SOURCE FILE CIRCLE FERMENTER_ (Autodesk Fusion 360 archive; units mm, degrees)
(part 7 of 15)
sketch "Schizzo22" plane through (0, -90, 0) normal (0, -1, 0) x axis (1, 0, 0)
  line L1 (160, -63.5) -> (85, -63.5)
  line L2 (160, 91.5) -> (160, -63.5)
  line L3 (85, 91.5) -> (160, 91.5)
  line L4 (0, 91.5) -> (85, 91.5)
  line L5 (0, 81.5) -> (0, 91.5)
  line L6 (95, 81.5) -> (0, 81.5)
  curve K1 (125, 51.5) -> (95, 81.5)
  line L7 (125, -23.5) -> (125, 51.5)
  curve K2 (125, -23.5) -> (95, -53.5)
  line L8 (0, -53.5) -> (95, -53.5)
  line L9 (0, -63.5) -> (0, -53.5)
  line L10 (85, -63.5) -> (0, -63.5)
  line L11 (142, 80) -> (0, 80)
  line L12 (0, 64) -> (142, 64)
  line L13 (0, 80) -> (0, 64)
  curve K3 (140.5791, 76.7542) -> (140.5791, 75.2458)
  curve K4 (143, 79) -> (142, 80)
  line L14 (143, 65) -> (143, 79)
  curve K5 (142, 64) -> (143, 65)
  circle C1 centre (47.5, 86.5) radius 3.35
  circle C2 centre (130, 51.5) radius 3.35
  circle C3 centre (130, -23.5) radius 3.35
  circle C4 centre (47.5, -58.5) radius 3.35
  circle C5 centre (139, 76) radius 1.5
  circle C6 centre (139, 68) radius 1.5
  arc A1 centre (139, 76) radius 1.75 clockwise from (140.5791, 76.7542) to (140.5791, 75.2458)
  circle C7 centre (139, 76) radius 1.75
  circle C8 centre (139, 68) radius 1.75
  circle C9 centre (139, 76) radius 1.75
  circle C10 centre (139, 68) radius 1.75
  concentric C5 A1
  concentric C6 C8
  dimension "d743_1" diameter C5 = 3
  dimension "d744_1" diameter C6 = 3
offset_faces "FacceDiOffset2" distance 1 named "d748_1"
extrude "Estrusione18" cut sketch "Schizzo22" profile of C5 C6 blind -7.192 named "d746_1" from offset -0.8 named "d745_1"
component_from_bodies "Corpo->Comp1"
component_from_bodies "Corpo->Comp2"
copy_paste "CopiaIncolla1"
copy_paste "CopiaIncolla2"
sketch "Schizzo23" plane through (0, -90, 0) normal (0, -1, 0) x axis (1, 0, 0)
  line L1 (160, -63.5) -> (85, -63.5)
  line L2 (160, 91.5) -> (160, -63.5)
  line L3 (85, 91.5) -> (160, 91.5)
  line L4 (0, 91.5) -> (85, 91.5)
  line L5 (0, 81.5) -> (0, 91.5)
  line L6 (95, 81.5) -> (0, 81.5)
  curve K1 (125, 51.5) -> (95, 81.5)
  line L7 (125, -23.5) -> (125, 51.5)
  curve K2 (125, -23.5) -> (95, -53.5)
  line L8 (0, -53.5) -> (95, -53.5)
  line L9 (0, -63.5) -> (0, -53.5)
  line L10 (85, -63.5) -> (0, -63.5)
  circle C1 centre (47.5, 86.5) radius 3.35
  circle C2 centre (130, 51.5) radius 3.35
  circle C3 centre (130, -23.5) radius 3.35
  circle C4 centre (47.5, -58.5) radius 3.35
  circle C5 centre (139, -4) radius 1.5
  circle C6 centre (139, -12) radius 1.5
  circle C7 centre (139, -12) radius 1.75
  circle C8 centre (139, -4) radius 1.75
  circle C9 centre (139, -12) radius 1.75
  point P19 (139, -12)
  point P20 (139, -12)
  concentric C5 C8
  coincident P19 P20
  dimension "d749_1" diameter C5 = 3
  dimension "d750_1" diameter C6 = 3
extrude "Estrusione19" cut sketch "Schizzo23" profile of C5 C6 against normal blind 9.545 named "d751_1"
sketch "Schizzo24" plane through (0, -88.4, 0) normal (0, 1, 0) x axis (-1, 0, 0)
  line L1 (-140.6, 91.5) -> (-140.6, -63.5)
  line L2 (-150.8209, 91.5) -> (-140.6, 91.5)
  line L3 (-150.8209, 41.5) -> (-150.8209, 91.5)
  line L4 (-150.8209, -13.5) -> (-150.8209, 41.5)
  line L5 (-150.8209, -13.5) -> (-150.8209, -63.5)
  line L6 (-140.6, -63.5) -> (-150.8209, -63.5)
  line L7 (-160, -63.5) -> (-85, -63.5)
  line L8 (-160, 91.5) -> (-160, -63.5)
  line L9 (-85, 91.5) -> (-160, 91.5)
  line L10 (0, 91.5) -> (-85, 91.5)
  line L11 (0, 81.5) -> (0, 91.5)
  line L12 (-95, 81.5) -> (0, 81.5)
  curve K1 (-125, 51.5) -> (-95, 81.5)
  line L13 (-125, -23.5) -> (-125, 51.5)
  curve K2 (-125, -23.5) -> (-95, -53.5)
  line L14 (0, -53.5) -> (-95, -53.5)
  line L15 (0, -63.5) -> (0, -53.5)
  line L16 (-85, -63.5) -> (0, -63.5)
  line L17 (-139, 78.5) -> (-139, -14.5)
  circle C1 centre (-139, 76) radius 1.5
  circle C2 centre (-139, 68) radius 1.5
  circle C3 centre (-139, 68) radius 2.5
  circle C4 centre (-139, 76) radius 2.5
  circle C5 centre (-139, -4) radius 1.5
  circle C6 centre (-139, -12) radius 1.5
  circle C7 centre (-139, -4) radius 1.5
  circle C8 centre (-139, -12) radius 1.5
  circle C9 centre (-47.5, 86.5) radius 3.35
  circle C10 centre (-130, 51.5) radius 3.35
  circle C11 centre (-130, -23.5) radius 3.35
  circle C12 centre (-47.5, -58.5) radius 3.35
  circle C13 centre (-139, -4) radius 2.5
  circle C14 centre (-139, -12) radius 2.5
  point P34 (-139, -14.5)
  point P35 (-139, 78.5)
  concentric C2 C3
  concentric C1 C4
  concentric C5 C13
  concentric C8 C14
  coincident C14 P34
  coincident C4 P35
  vertical L17
  dimension "d758_1" diameter C3 = 5
  dimension "d759_1" diameter C4 = 5
  dimension "d760_1" diameter C13 = 5
  dimension "d761_1" diameter C14 = 5
extrude "Estrusione20" add sketch "Schizzo24" profile of L1 C1 C2 C3 C4 C5 C6 C7 C8 C13 C14 L17 to an object
sketch "Schizzo25" plane through (0, -90, 0) normal (0, -1, 0) x axis (1, 0, 0)
  line L1 (160, -63.5) -> (85, -63.5)
  line L2 (160, 91.5) -> (160, -63.5)
  line L3 (85, 91.5) -> (160, 91.5)
  line L4 (0, 91.5) -> (85, 91.5)
  line L5 (0, 81.5) -> (0, 91.5)
  line L6 (95, 81.5) -> (0, 81.5)
  curve K1 (125, 51.5) -> (95, 81.5)
  line L7 (125, -23.5) -> (125, 51.5)
  curve K2 (125, -23.5) -> (95, -53.5)
  line L8 (0, -53.5) -> (95, -53.5)
  line L9 (0, -63.5) -> (0, -53.5)
  line L10 (85, -63.5) -> (0, -63.5)
  curve K3 (139, -2.5) -> (139, -2.5)
  circle C1 centre (139, -4) radius 1.5
  circle C2 centre (139, -12) radius 1.5
  circle C3 centre (47.5, 86.5) radius 3.35
  circle C4 centre (130, 51.5) radius 3.35
  circle C5 centre (130, -23.5) radius 3.35
  circle C6 centre (47.5, -58.5) radius 3.35
  circle C7 centre (139, -12) radius 1.5
extrude "Estrusione21" add sketch "Schizzo25" profile of C1 C2 K3 C7 against normal blind 0.8 named "d765_1"
work_plane "Piano di lavoro7" AlongDistance -5 named "d767_1"
sketch "Schizzo26" plane through (0, -85, 0) normal (0, -1, 0) x axis (-1, 0, 0)
  curve K1 (-140.3526, 4.6485) -> (-140.4601, 4.3436)
  circle C1 centre (-139, -76) radius 1.5
  circle C2 centre (-139, -68) radius 1.5
  circle C3 centre (-139, 12) radius 1.5
  circle C4 centre (-139, 4) radius 2.3
  circle C5 centre (-139, 12) radius 2.3
  circle C6 centre (-139, -68) radius 2.3
  circle C7 centre (-139, -76) radius 2.3
  arc A1 centre (-139, 4) radius 1.5 clockwise from (-140.3526, 4.6485) to (-140.4601, 4.3436)
  concentric C3 C5
  concentric C2 C6
  concentric C1 C7
  dimension "d768_1" diameter C4 = 4.6
  dimension "d769_1" diameter C5 = 4.6
  dimension "d770_1" diameter C6 = 4.6
  dimension "d771_1" diameter C7 = 4.6
extrude "Estrusione22" cut sketch "Schizzo26" profile of C1 C2 C3 C4 C5 C6 C7 against normal blind 5.06 named "d772_1"
sketch "Schizzo27" plane through (0, -85, 0) normal (0, 1, 0) x axis (-1, 0, 0)
  line L1 (-137.1434, -13.3576) -> (-137.1434, -10.6424)
  line L2 (-137.1434, -5.3576) -> (-137.1434, -2.6424)
  line L3 (-137.1434, 74.6424) -> (-137.1434, 77.3576)
  line L4 (-137.1434, 66.6424) -> (-137.1434, 69.3576)
  arc A1 centre (-139, -12) radius 2.3 clockwise from (-137.1434, -13.3576) to (-137.1434, -10.6424)
  circle C1 centre (-139, -12) radius 1.5
  arc A2 centre (-139, -4) radius 2.3 clockwise from (-137.1434, -5.3576) to (-137.1434, -2.6424)
  circle C2 centre (-139, -4) radius 1.5
  arc A3 centre (-139, 76) radius 2.3 clockwise from (-137.1434, 74.6424) to (-137.1434, 77.3576)
  circle C3 centre (-139, 76) radius 1.5
  arc A4 centre (-139, 68) radius 2.3 clockwise from (-137.1434, 66.6424) to (-137.1434, 69.3576)
  circle C4 centre (-139, 68) radius 1.5
  circle C5 centre (-139, 68) radius 2
  circle C6 centre (-139, 76) radius 2
  circle C7 centre (-139, -4) radius 2
  circle C8 centre (-139, -12) radius 2
  concentric A4 C5
  concentric A3 C6
  concentric A2 C7
  concentric A1 C8
  dimension "d792_1" diameter C5 = 4
  dimension "d793_1" diameter C6 = 4
  dimension "d794_1" diameter C7 = 4
  dimension "d795_1" diameter C8 = 4
extrude "Estrusione24" cut sketch "Schizzo27" profile of L1 C1 L2 C2 L3 C3 L4 C4 C5 C6 C7 C8 against normal blind 4.2 named "d796_1"
extrude "Estrusione25" add sketch "Schizzo2" to an object
extrude "Estrusione26" add sketch "Schizzo3" against normal blind 155 named "d848_1"
extrude "Estrusione27" add sketch "Schizzo4" profile of L1 L3 A1 L11 L12 L13 A2 L14 A3 L15 A4 L16 A5 L17 A6 L18 A7 L19 A8 L20 L21 L22 against normal blind 7 named "d850_1"
mirror "Specchio2" mirrorStitchTolerance 0.1 named "d710_1"
mirror "Specchio2" mirrorStitchTolerance 0.1 named "d777_1"
component_from_bodies "Corpo->Comp1"
base_feature "Lavorazione di base1"
sketch "Schizzo2" plane through (0, 88.4, 0) normal (0, -1, 0) x axis (1, 0, 0)
  line L1 (0, -53.5) -> (95, -53.5)
  line L2 (0, -63.5) -> (0, -53.5)
  line L3 (95, -63.5) -> (0, -63.5)
  curve K1 (95, -63.5) -> (135, -23.5)
  line L4 (135, 51.5) -> (135, -23.5)
  curve K2 (95, 91.5) -> (135, 51.5)
  line L5 (0, 91.5) -> (95, 91.5)
  line L6 (0, 81.5) -> (0, 91.5)
  line L7 (95, 81.5) -> (0, 81.5)
  curve K3 (125, 51.5) -> (95, 81.5)
  line L8 (125, -23.5) -> (125, 51.5)
  curve K4 (125, -23.5) -> (95, -53.5)
  line L9 (95, -63) -> (0, -63)
  curve K5 (95, -63) -> (134.5, -23.5)
  line L10 (134.5, 51.5) -> (134.5, -23.5)
  line L11 (0, 91) -> (0, -63)
  curve K6 (95, 91) -> (134.5, 51.5)
  line L12 (0, 91) -> (95, 91)
  circle C1 centre (47.5, 86.5) radius 1.75
  circle C2 centre (130, 51.5) radius 1.75
  circle C3 centre (130, -23.5) radius 1.75
  circle C4 centre (47.5, -58.5) radius 1.75
  point P24 (0, 91)
  coincident L6 P24
  perpendicular L9 L11
  dimension "d782_1" = -0.5
  dimension "d785_1" = -0.5
extrude "Estrusione2" new body sketch "Schizzo2" profile of C1 C2 C3 C4 L1 L2 L6 L7 K3 L8 K4 K5 L9 L10 L11 L12 K6 along normal blind 3 named "d783_1"
component_from_bodies "Corpo->Comp2"
copy_paste "CopiaIncolla2"
joint "Assembla2" alignAngle 0 named "d786_1" alignOffsetX 0 named "d787_1" alignOffsetY 0 named "d788_1" alignOffsetZ 0 named "d789_1"
remove_instance "RimuoviIstanza1"
component_from_bodies "Corpo->Comp1"
base_feature "Lavorazione di base1" bodies "PROFILO BASE"
mirror "Specchio1" mirrorStitchTolerance 0.1 named "d819_1"
mirror "Specchio1" mirrorStitchTolerance 0.1 named "d821_2"
mirror_component "SpecchiaComponente1"
derived_instance "DerivedInstance1"
mirror_component "SpecchiaComponente2"
derived_instance "DerivedInstance2"
mirror "Specchio1" mirrorStitchTolerance 0.1 named "d823_1"
mirror_component "SpecchiaComponente3"
derived_instance "DerivedInstance3"
derived_instance "DerivedInstance4"
derived_instance "DerivedInstance5"
derived_instance "DerivedInstance6"
sketch "Schizzo1" plane through (0, -72.4, 0) normal (0, 1, 0) x axis (-1, 0, 0)
  line L1 (142, 64) -> (-142, 64)
  curve K1 (142, 64) -> (143, 65)
  line L2 (143, 79) -> (143, 65)
  curve K2 (143, 79) -> (142, 80)
  line L3 (-142, 80) -> (142, 80)
  curve K3 (-143, 79) -> (-142, 80)
  line L4 (-143, 65) -> (-143, 79)
  curve K4 (-142, 64) -> (-143, 65)
  line L5 (142, 64) -> (-142, 64)
  curve K5 (142, 64) -> (143, 65)
  line L6 (143, 79) -> (143, 65)
  curve K6 (143, 79) -> (142, 80)
  line L7 (-142, 80) -> (142, 80)
  curve K7 (-143, 79) -> (-142, 80)
  line L8 (-143, 65) -> (-143, 79)
  curve K8 (-142, 64) -> (-143, 65)
  circle C1 centre (139, 76) radius 1.75
  circle C2 centre (139, 68) radius 1.75
  circle C3 centre (-139, 68) radius 1.75
  circle C4 centre (-139, 76) radius 1.75
  circle C5 centre (139, 76) radius 1.75
  circle C6 centre (139, 68) radius 1.75
  circle C7 centre (-139, 68) radius 1.75
  circle C8 centre (-139, 76) radius 1.75
joint "Assembla4" alignAngle 0 named "d903_1" alignOffsetX 0 named "d904_1" alignOffsetY 0 named "d905_1" alignOffsetZ 0 named "d906_1"
sketch "Schizzo1" plane through (0, 0, -88.5) normal (0, 0, -1) x axis (1, 0, 0)
  line L1 (95, 55) -> (0, 55)
  curve K1 (95, 55) -> (125, 25)
  line L2 (125, -25) -> (125, 25)
  curve K2 (95, -55) -> (125, -25)
  line L3 (0, -55) -> (95, -55)
  line L4 (0, -65) -> (0, -55)
  line L5 (85, -65) -> (0, -65)
  line L6 (160, -65) -> (85, -65)
  line L7 (160, 65) -> (160, -65)
  line L8 (85, 65) -> (160, 65)
  line L9 (0, 65) -> (85, 65)
  line L10 (0, 55) -> (0, 65)
  curve K3 (95, -55) -> (125, -25)
  line L11 (95, -55) -> (0, -55)
  line L12 (125, -25) -> (125, 25)
  line L13 (135, -25) -> (135, 0)
  curve K4 (95, -65) -> (135, -25)
  line L14 (95, -65) -> (0, -65)
  line L15 (135, 0) -> (125, 0)
  line L16 (122, -25) -> (122, 0)
  curve K5 (95, -52) -> (122, -25)
  line L17 (95, -52) -> (0, -52)
  line L18 (122, 0) -> (125, 0)
  line L19 (0, -52) -> (0, -65)
  circle C1 centre (47.5, -60) radius 3.35
  circle C2 centre (130, -25) radius 3.35
  circle C3 centre (130, 25) radius 3.35
  circle C4 centre (47.5, 60) radius 3.35
  circle C5 centre (130, -25) radius 1.75
  circle C6 centre (47.5, -60) radius 1.75
  point P25 (125, 0)
  point P12 (0, -65)
  point P31 (0, -65)
  midpoint L2 P25
  perpendicular L13 L15
  perpendicular L16 L18
  coincident P12 P31
  perpendicular L17 L19
extrude "Estrusione1" new body sketch "Schizzo1" profile of C1 C2 L2 K2 L3 L4 L5 L6 K3 L11 L12 L13 K4 L14 L15 L16 K5 L17 L18 L19 C5 C6 along normal blind 15 named "d826_1"
sketch "Schizzo2" plane through (0, 0, 0) normal (0, -1, 0) x axis (1, 0, 0)
  line L1 (122, -88.5) -> (135, -88.5)
  line L2 (122, -103.5) -> (122, -88.5)
  line L3 (135, -103.5) -> (122, -103.5)
  line L4 (135, -88.5) -> (135, -103.5)
  line L5 (124, -88.5) -> (124, -103.5)
  curve K1 (135, -91) -> (135, -88.5)
  curve K2 (129.5, -94.5) -> (135, -91)
  curve K3 (124, -99.2) -> (129.5, -94.5)
  curve K4 (124, -101.7) -> (124, -99.2)
  curve K5 (124, -101.7) -> (135, -88.5)
  line L6 (124, -103.5) -> (124, -101.7)
  point P6 (124, -103.5)
  point P7 (124, -88.5)
  point P8 (135, -91)
  point P10 (124, -99.2)
  point P2 (135, -88.5)
  point P9 (129.5, -94.5)
  point P11 (124, -101.7)
  coincident L3 P6
  coincident L1 P7
  perpendicular L1 L5
  coincident L4 P8
  coincident L5 P10
  vertical K4
  dimension "d828_1" distance L2 L5 = 2
  dimension "d830_1" distance P2 P8 = 2.5
  dimension "d831_1" distance P8 P9 = 3.5
  dimension "d832_1" distance P9 P10 = 4.7
  dimension "d833_1" distance L4 P9 = 5.5 (= "d881_1 / 2")
  dimension "d852_1" distance P6 P11 = 1.8
  dimension "d853_1" distance P10 P11 = 2.5
  dimension "d881_1" distance L4 L5 = 11
sweep "Sweep1" sketch "Schizzo2" TwistAngle 0 named "d838_1" TaperAngle 0 named "d839_1"
sketch "Schizzo3" plane through (0, 0, -88.5) normal (0, 0, 1) x axis (-1, 0, 0)
  line L1 (0, -65) -> (-95, -65)
  line L2 (0, -52) -> (0, -65)
  line L3 (-95, -52) -> (0, -52)
  curve K1 (-95, -52) -> (-122, -25)
  line L4 (-122, 0) -> (-122, -25)
  line L5 (-135, 0) -> (-122, 0)
  line L6 (-135, -25) -> (-135, 0)
  curve K2 (-95, -65) -> (-135, -25)
  line L7 (-95, -54.4) -> (0, -54.4)
  curve K3 (-95, -54.4) -> (-124.4, -25)
  line L8 (-124.4, 0) -> (-124.4, -25)
  line L9 (-122, 0) -> (-124.4, 0)
  line L10 (0, -54.4) -> (0, -52)
  circle C1 centre (-130, -25) radius 1.75
  circle C2 centre (-47.5, -60) radius 1.75
  point P9 (-122, 0)
  point P16 (-122, 0)
  point P6 (0, -52)
  point P17 (0, -52)
  coincident P9 P16
  perpendicular L4 L9
  coincident P6 P17
  perpendicular L7 L10
  dimension "d840_1" = -2.4
extrude "Estrusione2" add sketch "Schizzo3" profile of L2 L3 K1 L4 L5 L8 L7 K3 L9 L10 along normal blind 1.6 named "d841_1"
extrude "Estrusione4" cut of existing geometry blind -0.2 named "d854_1"
work_plane "Piano di lavoro1" AlongDistance -1.2 named "d856_1"
sketch "Schizzo5" plane through (0, 0, -89.7) normal (0, 0, 1) x axis (1, 0, 0)
  circle C1 centre (130, 25) radius 3
  circle C2 centre (47.5, 60) radius 3
  circle C3 centre (47.5, 60) radius 1.75
  circle C4 centre (130, 25) radius 1.75
  point P3 (47.5, 60)
  point P4 (47.5, 60)
  point P2 (130, 25)
  point P5 (130, 25)
  coincident P3 P4
  coincident P2 P5
  dimension "d857_1" diameter C1 = 6
  dimension "d858_1" diameter C2 = 6 (= "d857_1")
extrude "Estrusione5" cut sketch "Schizzo5" profile of C1 C2 C3 against normal blind 16.363 named "d860_1"
joint "Assembla5" alignAngle 0 named "d1241_1" alignOffsetX 0 named "d1242_1" alignOffsetY 0 named "d1243_1" alignOffsetZ 0 named "d1244_1"
chamfer "Smusso1" distance 1.25 named "d862_1"
fillet "Raccordo1" radius 0.2 named "d864_1"
extrude "Estrusione6" cut of existing geometry blind -1.4 named "d865_1"
sketch "Schizzo6" plane through (0, 0, 0) normal (0, -1, 0) x axis (1, 0, 0)
  line L1 (122, -88.5) -> (135, -88.5)
  line L2 (122, -103.5) -> (122, -88.5)
  line L3 (124, -103.5) -> (122, -103.5)
  line L4 (124, -101.7) -> (124, -103.5)
  curve K1 (135, -88.5) -> (124, -101.7)
  line L5 (122, -101.7) -> (124, -101.7)
  line L6 (124.4, -88.5) -> (122, -88.5)
  curve K2 (124.4, -91.5) -> (124.4, -88.5)
  curve K3 (123.2, -95.1) -> (124.4, -91.5)
  curve K4 (122, -98.7) -> (123.2, -95.1)
  curve K5 (122, -101.7) -> (122, -98.7)
  curve K6 (122, -101.7) -> (124.4, -88.5)
  point P6 (124, -101.7)
  point P7 (124, -101.7)
  point P8 (122, -101.7)
  point P3 (122, -88.5)
  point P9 (122, -88.5)
  point P10 (124.4, -88.5)
  point P13 (122, -98.7)
  point P11 (124.4, -91.5)
  point P12 (123.2, -95.1)
  coincident P6 P7
  coincident L2 P8
  perpendicular L2 L5
  coincident P3 P9
  coincident L1 P10
  vertical K5
  vertical K2
  dimension "d867_1" distance P9 P10 = 2.4
  dimension "d868_1" distance P8 P13 = 3
  dimension "d869_1" distance P10 P11 = 3
  dimension "d870_1" distance P11 P12 = 3.6 (= "d873_1 / 2")
  dimension "d873_1" distance P11 P13 = 7.2
  dimension "d874_1" distance L2 P12 = 1.2 (= "d867_1 / 2")
sweep "Sweep2" sketch "Schizzo6" TwistAngle 0 named "d879_1" TaperAngle 0 named "d880_1"
mirror "Specchio1" mirrorStitchTolerance 0.1 named "d883_1"
mirror "Specchio2" mirrorStitchTolerance 0.1 named "d885_1"
component_from_bodies "Corpo->Comp1"
component_from_bodies "Corpo->Comp2"
sketch "Schizzo1" plane through (0, 0, 0) normal (-1, 0, 0) x axis (0, -1, 0)
  curve K1 (-52, -101.7) -> (-54.4, -88.5)
  line L1 (-65, -88.5) -> (-54.4, -88.5)
  curve K2 (-54, -101.7) -> (-65, -88.5)
  line L2 (-54, -103.5) -> (-54, -101.7)
  line L3 (-52, -103.5) -> (-54, -103.5)
  line L4 (-52, -101.7) -> (-52, -103.5)
  line L5 (-53, -101.7) -> (-59.7, -88.5)
  line L6 (-59.7, -101.6426) -> (-59.7, -88.5)
  line L7 (-53, -90.6394) -> (-53, -101.7)
  curve K3 (-59.7, -93) -> (-59.7, -88.5)
  curve K4 (-56.35, -95.1) -> (-59.7, -93)
  curve K5 (-53, -97.2) -> (-56.35, -95.1)
  curve K6 (-53, -101.7) -> (-53, -97.2)
  curve K7 (-53, -101.7) -> (-59.7, -88.5)
  line L8 (-54, -101.7) -> (-52, -101.7)
  line L9 (-53, -103.5) -> (-53, -101.7)
  line L10 (-25, -88.5) -> (25, -88.5)
  line L11 (-25, -101.7) -> (-25, -88.5)
  line L12 (25, -101.7) -> (-25, -101.7)
  line L13 (25, -101.7) -> (25, -88.5)
  line L14 (0, -127.2244) -> (0, -88.5)
  line L15 (53, -103.5) -> (53, -101.7)
  curve K8 (53, -101.7) -> (59.7, -88.5)
  curve K9 (59.7, -93) -> (59.7, -88.5)
  curve K10 (56.35, -95.1) -> (59.7, -93)
  curve K11 (53, -97.2) -> (56.35, -95.1)
  curve K12 (53, -101.7) -> (53, -97.2)
  curve K13 (52, -101.7) -> (54.4, -88.5)
  line L16 (52, -103.5) -> (52, -101.7)
  line L17 (54, -103.5) -> (52, -103.5)
  line L18 (54, -101.7) -> (54, -103.5)
  curve K14 (54, -101.7) -> (65, -88.5)
  line L19 (54.4, -88.5) -> (65, -88.5)
  point P8 (-59.7, -88.5)
  point P12 (-59.7, -93)
  point P14 (-53, -97.2)
  point P3 (-52, -101.7)
  point P15 (-52, -101.7)
  point P5 (-54, -101.7)
  point P16 (-54, -101.7)
  point P9 (-53, -101.7)
  point P17 (-53, -103.5)
  point P22 (0, -88.5)
  point P26 (59.7, -88.5)
  point P24 (53, -101.7)
  point P25 (53, -103.5)
  point P13 (-56.35, -95.1)
  midpoint L1 P8
  perpendicular L1 L6
  coincident L6 P12
  coincident L7 P14
  vertical L7
  coincident P3 P15
  coincident P5 P16
  midpoint P9 L8
  midpoint L3 P17
  midpoint L10 P22
  perpendicular L10 L14
  symmetric P8 L14 P26
  symmetric P9 L14 P24
  symmetric K7 L14 K8
  symmetric P17 L14 P25
  dimension "d886_1" distance P8 P12 = 4.5 (= "d887_1")
  dimension "d887_1" distance P9 P14 = 4.5
  dimension "d888_1" distance P12 P14 = 4.2
  dimension "d889_1" distance P13 P14 = 2.1 (= "d888_1 / 2")
  dimension "d890_1" distance L6 P14 = 6.7
  dimension "d891_1" distance P12 P13 = 3.35 (= "d890_1 / 2")
extrude "Estrusione1" cut sketch "Schizzo1" profile of K1 L1 L3 L4 K7 L9 L15 K8 K13 L16 L17 L19 against normal blind 2.2 named "d892_1"
sketch "Schizzo1" plane through (0, 0, 0) normal (1, 0, 0) x axis (0, 1, 0)
  curve K1 (52, -101.7) -> (54.4, -88.5)
  line L1 (52, -103.5) -> (52, -101.7)
  line L2 (54, -103.5) -> (52, -103.5)
  line L3 (54, -101.7) -> (54, -103.5)
  curve K2 (54, -101.7) -> (65, -88.5)
  line L4 (54.4, -88.5) -> (65, -88.5)
  line L5 (59.7, -88.5) -> (54.4, -88.5)
  curve K3 (59.7, -88.5) -> (53, -101.7)
  line L6 (53, -103.5) -> (53, -101.7)
  line L7 (52, -103.5) -> (53, -103.5)
  line L8 (52, -101.7) -> (52, -103.5)
  curve K4 (52, -101.7) -> (54.4, -88.5)
  curve K5 (-54.4, -88.5) -> (-52, -101.7)
  line L9 (-52, -103.5) -> (-52, -101.7)
  line L10 (-53, -103.5) -> (-52, -103.5)
  line L11 (-53, -101.7) -> (-53, -103.5)
  curve K6 (-53, -101.7) -> (-59.7, -88.5)
  line L12 (-54.4, -88.5) -> (-59.7, -88.5)
extrude "Estrusione1" add sketch "Schizzo1" profile of K1 L1 L2 L4 L5 K3 L6 L7 L8 K4 K5 L9 L10 L11 K6 L12 along normal blind 2 named "d894_1"
sketch "Schizzo1" plane through (148.4, 0, 0) normal (1, 0, 0) x axis (0, 1, 0)
  curve K1 (-83.9651, 77.4206) -> (-79.9057, 75.4498)
  line L1 (-83.9651, 76.5591) -> (-83.9651, 77.4206)
  curve K2 (-83.9651, 76.5591) -> (-84.564, 75.5072)
  curve K3 (-84.564, 67.4928) -> (-83.9651, 66.4409)
  line L2 (-83.9651, 65.58) -> (-83.9651, 66.4409)
  curve K4 (-79.9058, 67.5505) -> (-83.9651, 65.58)
  curve K5 (-79.9057, 75.4498) -> (-79.9058, 67.5505)
  circle C1 centre (-81.5735, 71.5) radius 0.75
  arc A1 centre (-81.5735, 71.5) radius 5 clockwise from (-84.564, 67.4928) to (-84.564, 75.5072)
  circle C2 centre (-81.5735, -43.5) radius 0.75
  circle C3 centre (-81.5735, 71.5) radius 0.75
  circle C4 centre (81.5735, 71.5) radius 0.75
  circle C5 centre (81.5735, -43.5) radius 0.75
  circle C6 centre (-81.5735, 71.5) radius 2
  circle C7 centre (-81.5735, -43.5) radius 2
  circle C8 centre (81.5735, -43.5) radius 2
  circle C9 centre (81.5735, 71.5) radius 2
  concentric C1 C6
  concentric C2 C7
  concentric C5 C8
  concentric C4 C9
  dimension "d907_1" diameter C6 = 4
  dimension "d914_1" diameter C7 = 4
  dimension "d915_1" diameter C8 = 4
  dimension "d916_1" diameter C9 = 4
extrude "Estrusione1" cut sketch "Schizzo1" profile of C1 C3 C6 blind -4 named "d908_1"
component_insert "Inserimento componente1"
joint "Assembla1" alignAngle -90 named "d910_1" alignOffsetX 0 named "d911_1" alignOffsetY 0 named "d912_1" alignOffsetZ 0 named "d913_1"
extrude "Estrusione2" cut sketch "Schizzo1" profile of C2 C4 C5 C7 C8 C9 blind -4 named "d917_1"
sketch "Schizzo2" plane through (-160, 0, 0) normal (-1, 0, 0) x axis (0, -1, 0)
  line L1 (-65, 116.5) -> (65, 116.5)
  curve K1 (-65, 116.5) -> (-90, 91.5)
  line L2 (-90, -63.5) -> (-90, 91.5)
  curve K2 (-65, -88.5) -> (-90, -63.5)
  line L3 (65, -88.5) -> (-65, -88.5)
  curve K3 (65, -88.5) -> (90, -63.5)
  line L4 (90, 91.5) -> (90, -63.5)
  curve K4 (65, 116.5) -> (90, 91.5)
  line L5 (65, 114.9) -> (-65, 114.9)
  curve K5 (88.4, 91.5) -> (65, 114.9)
  line L6 (88.4, -63.5) -> (88.4, 91.5)
  curve K6 (88.4, -63.5) -> (65, -86.9)
  line L7 (-65, -86.9) -> (65, -86.9)
  curve K7 (-88.4, -63.5) -> (-65, -86.9)
  line L8 (-88.4, 91.5) -> (-88.4, -63.5)
  curve K8 (-88.4, 91.5) -> (-65, 114.9)
extrude "Estrusione2" new body sketch "Schizzo2" along normal blind 20 named "d919_1"
work_plane "Piano di lavoro1" AlongDistance -25 named "d921_1"
sketch "Schizzo3" plane through (0, 0, -63.5) normal (0, 0, -1) x axis (-1, 0, 0)
  curve K1 (160, 88.4) -> (142.5, 81.4)
  line L1 (148.4, 79.5735) -> (148.4, 83.5735)
  line L2 (160, 90) -> (85, 90)
  line L3 (85, 90) -> (160, 90)
  line L4 (0, 90) -> (85, 90)
  line L5 (95, 90) -> (0, 90)
  line L6 (125, 90) -> (95, 90)
  line L7 (125, 90) -> (95, 90)
  line L8 (0, 90) -> (95, 90)
  line L9 (85, 90) -> (0, 90)
  line L10 (35.35, 90) -> (28.65, 90)
  line L11 (133.35, 90) -> (126.65, 90)
  line L12 (98.35, 90) -> (91.65, 90)
  line L13 (91.65, 90) -> (98.35, 90)
  line L14 (126.65, 90) -> (133.35, 90)
  line L15 (28.65, 90) -> (35.35, 90)
  line L16 (148.4, 90) -> (148.4, 77.9)
  curve K2 (160, 86.8) -> (142.5, 79.8)
  line L17 (150, 90) -> (150, 77.9)
  line L18 (149.7497, 77.9) -> (150, 77.9)
  line L19 (148.4, 77.9) -> (149.7497, 77.9)
  line L20 (160, 88.4) -> (160, 86.8)
  point P18 (148.4, 90)
  point P5 (148.4, 79.5735)
  point P3 (160, 88.4)
  point P24 (160, 88.4)
  point P17 (148.4, 77.9)
  coincident L3 P18
  perpendicular L3 L16
  coincident P5 L16
  perpendicular L17 L18
  perpendicular L16 L19
  coincident P3 P24
  perpendicular L19 L20
  dimension "d922_1" distance P17 P18 = 12.1
  dimension "d923_1" = 1.6
  dimension "d924_1" = 1.6
sweep "Sweep1" sketch "Schizzo3" TwistAngle 0 named "d929_1" TaperAngle 0 named "d930_1"
sketch "Schizzo4" plane through (-180, 0, 0) normal (-1, 0, 0) x axis (0, -1, 0)
  line L1 (65, 114.9) -> (-65, 114.9)
  curve K1 (88.4, 91.5) -> (65, 114.9)
  line L2 (88.4, -63.5) -> (88.4, 91.5)
  curve K2 (65, -86.9) -> (88.4, -63.5)
  line L3 (-65, -86.9) -> (65, -86.9)
  curve K3 (-88.4, -63.5) -> (-65, -86.9)
  line L4 (-88.4, 91.5) -> (-88.4, -63.5)
  curve K4 (-65, 114.9) -> (-88.4, 91.5)
  line L5 (90, 91.5) -> (90, -63.5)
  curve K5 (65, 116.5) -> (90, 91.5)
  line L6 (-65, 116.5) -> (65, 116.5)
  curve K6 (-90, 91.5) -> (-65, 116.5)
  line L7 (-90, -63.5) -> (-90, 91.5)
  curve K7 (-65, -88.5) -> (-90, -63.5)
  line L8 (65, -88.5) -> (-65, -88.5)
  curve K8 (90, -63.5) -> (65, -88.5)
  line L9 (-65, -86.4) -> (65, -86.4)
  curve K9 (-87.9, -63.5) -> (-65, -86.4)
  line L10 (-87.9, 91.5) -> (-87.9, -63.5)
  curve K10 (-65, 114.4) -> (-87.9, 91.5)
  line L11 (65, 114.4) -> (-65, 114.4)
  curve K11 (87.9, 91.5) -> (65, 114.4)
  line L12 (87.9, -63.5) -> (87.9, 91.5)
  curve K12 (65, -86.4) -> (87.9, -63.5)
  dimension "d931_1" = 0.5
extrude "Estrusione3" new body sketch "Schizzo4" profile of L9 K9 K12 L10 K11 L11 K10 L12 against normal blind 3 named "d932_1"
offset_faces "FacceDiOffset1" distance -0.2 named "d934_1"
offset_faces "FacceDiOffset1" distance -0.2 named "d936_1"
sketch "Schizzo1" plane through (158, 0, 0) normal (1, 0, 0) x axis (0, 1, 0)
  line L1 (86.7, 91.3) -> (86.7, -63.3)
  line L2 (82.7, 91.3) -> (86.7, 91.3)
  curve K1 (64.8, 109.2) -> (82.7, 91.3)
  line L3 (64.8, 113.2) -> (64.8, 109.2)
  line L4 (-64.8, 113.2) -> (64.8, 113.2)
  line L5 (-64.8, 109.2) -> (-64.8, 113.2)
  curve K2 (-82.7, 91.3) -> (-64.8, 109.2)
  line L6 (-86.7, 91.3) -> (-82.7, 91.3)
  line L7 (-86.7, -63.3) -> (-86.7, 91.3)
  line L8 (-82.7, -63.3) -> (-86.7, -63.3)
  curve K3 (-64.8, -81.2) -> (-82.7, -63.3)
  line L9 (-64.8, -85.2) -> (-64.8, -81.2)
  line L10 (64.8, -85.2) -> (-64.8, -85.2)
  line L11 (64.8, -81.2) -> (64.8, -85.2)
  curve K4 (82.7, -63.3) -> (64.8, -81.2)
  line L12 (86.7, -63.3) -> (82.7, -63.3)
  circle C1 centre (81.5735, 14) radius 1.75
  circle C2 centre (-81.5735, 14) radius 1.75
  circle C3 centre (-81.5735, 71.5) radius 1.75
  circle C4 centre (-45, 108.0735) radius 1.75
  circle C5 centre (45, 108.0735) radius 1.75
  circle C6 centre (81.5735, 71.5) radius 1.75
  circle C7 centre (0, 108.0735) radius 1.75
  circle C8 centre (0, -80.0735) radius 1.75
  circle C9 centre (81.5735, -43.5) radius 1.75
  circle C10 centre (45, -80.0735) radius 1.75
  circle C11 centre (-45, -80.0735) radius 1.75
  circle C12 centre (-81.5735, -43.5) radius 1.75
offset_faces "FacceDiOffset1" distance -0.2 named "d937_1"
offset_faces "FacceDiOffset2" distance -0.2 named "d938_1"
offset_faces "FacceDiOffset3" distance -0.2 named "d939_1"
offset_faces "FacceDiOffset4" distance -0.2 named "d940_1"
remove_instance "RimuoviIstanza2"
extrude "Estrusione3" add of existing geometry blind 1.8 named "d945_1"
extrude "Estrusione4" add of existing geometry blind 0.4 named "d947_1"
component_from_bodies "Corpo->Comp1"
sketch "Schizzo1" plane through (-148.4, 0, 0) normal (1, 0, 0) x axis (0, 1, 0)
  line L1 (82.0401, -63.5) -> (82.0401, 91.5)
  curve K1 (82.0401, -63.5) -> (65, -80.5401)
  line L2 (-65, -80.5401) -> (65, -80.5401)
  curve K2 (-65, -80.5401) -> (-82.0401, -63.5)
  line L3 (-82.0401, 91.5) -> (-82.0401, -63.5)
  curve K3 (-82.0401, 91.5) -> (-65, 108.5401)
  line L4 (65, 108.5401) -> (-65, 108.5401)
  curve K4 (65, 108.5401) -> (82.0401, 91.5)
  curve K5 (65, 110.4651) -> (83.9651, 91.5)
  line L5 (-65, 110.4651) -> (65, 110.4651)
  curve K6 (-83.9651, 91.5) -> (-65, 110.4651)
  line L6 (-83.9651, -63.5) -> (-83.9651, 91.5)
  curve K7 (-65, -82.4651) -> (-83.9651, -63.5)
  line L7 (65, -82.4651) -> (-65, -82.4651)
  curve K8 (83.9651, -63.5) -> (65, -82.4651)
  line L8 (83.9651, 91.5) -> (83.9651, -63.5)
  line L9 (77.9, -63.5) -> (77.9, 91.5)
  curve K9 (65, -76.4) -> (77.9, -63.5)
  line L10 (-65, -76.4) -> (65, -76.4)
  curve K10 (-65, -76.4) -> (-77.9, -63.5)
  line L11 (-77.9, 91.5) -> (-77.9, -63.5)
  curve K11 (-65, 104.4) -> (-77.9, 91.5)
  line L12 (65, 104.4) -> (-65, 104.4)
  curve K12 (65, 104.4) -> (77.9, 91.5)
  line L13 (86.9365, 91.3) -> (86.9365, -63.3)
  line L14 (82.7, 91.3) -> (86.9365, 91.3)
  curve K13 (82.7, 91.3) -> (64.8, 109.2)
  line L15 (64.8, 113.4365) -> (64.8, 109.2)
  line L16 (-64.8, 113.4365) -> (64.8, 113.4365)
  line L17 (-64.8, 109.2) -> (-64.8, 113.4365)
  curve K14 (-64.8, 109.2) -> (-82.7, 91.3)
  line L18 (-86.9365, 91.3) -> (-82.7, 91.3)
  line L19 (-86.9365, -63.3) -> (-86.9365, 91.3)
  line L20 (-82.7, -63.3) -> (-86.9365, -63.3)
  curve K15 (-82.7, -63.3) -> (-64.8, -81.2)
  line L21 (-64.8, -85.4365) -> (-64.8, -81.2)
  line L22 (64.8, -85.4365) -> (-64.8, -85.4365)
  line L23 (64.8, -81.2) -> (64.8, -85.4365)
  curve K16 (64.8, -81.2) -> (82.7, -63.3)
  line L24 (86.9365, -63.3) -> (82.7, -63.3)
  line L25 (65, 103) -> (-65, 103)
  curve K17 (65, 103) -> (76.5, 91.5)
  line L26 (76.5, -63.5) -> (76.5, 91.5)
  curve K18 (65, -75) -> (76.5, -63.5)
  line L27 (-65, -75) -> (65, -75)
  curve K19 (-65, -75) -> (-76.5, -63.5)
  line L28 (-76.5, 91.5) -> (-76.5, -63.5)
  curve K20 (-65, 103) -> (-76.5, 91.5)
  circle C1 centre (81.5735, 14) radius 1.75
  circle C2 centre (-81.5735, 14) radius 1.75
  circle C3 centre (-81.5735, 71.5) radius 1.75
  circle C4 centre (-45, 108.0735) radius 1.75
  circle C5 centre (45, 108.0735) radius 1.75
  circle C6 centre (81.5735, 71.5) radius 1.75
  circle C7 centre (0, 108.0735) radius 1.75
  circle C8 centre (0, -80.0735) radius 1.75
  circle C9 centre (81.5735, -43.5) radius 1.75
  circle C10 centre (45, -80.0735) radius 1.75
  circle C11 centre (-45, -80.0735) radius 1.75
  circle C12 centre (-81.5735, -43.5) radius 1.75
  dimension "d979_1" = 1.4
extrude "Estrusione1" add sketch "Schizzo1" profile of L1 K1 L2 K2 L3 K3 L4 K4 K5 L5 K6 L6 K7 L7 K8 L8 L9 K9 L10 K10 L11 K11 L12 K12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 against normal blind 2.4 named "d949_1"
sketch "Schizzo5" plane through (-150.8, 0, 0) normal (-1, 0, 0) x axis (0, -1, 0)
  line L1 (-65, -82.1107) -> (65, -82.1107)
  curve K1 (65, -82.1107) -> (83.6107, -63.5)
  line L2 (83.6107, -63.5) -> (83.6107, 91.5)
  curve K2 (83.6107, 91.5) -> (65, 110.1107)
  line L3 (65, 110.1107) -> (-65, 110.1107)
  curve K3 (-65, 110.1107) -> (-83.6107, 91.5)
  line L4 (-83.6107, 91.5) -> (-83.6107, -63.5)
  curve K4 (-83.6107, -63.5) -> (-65, -82.1107)
  line L5 (-65, -81.6107) -> (65, -81.6107)
  curve K5 (-83.1107, -63.5) -> (-65, -81.6107)
  line L6 (-83.1107, 91.5) -> (-83.1107, -63.5)
  curve K6 (-65, 109.6107) -> (-83.1107, 91.5)
  line L7 (65, 109.6107) -> (-65, 109.6107)
  curve K7 (83.1107, 91.5) -> (65, 109.6107)
  line L8 (83.1107, -63.5) -> (83.1107, 91.5)
  curve K8 (65, -81.6107) -> (83.1107, -63.5)
  curve K9 (65, -75) -> (76.5, -63.5)
  line L9 (-65, -75) -> (65, -75)
  curve K10 (-76.5, -63.5) -> (-65, -75)
  line L10 (-76.5, 91.5) -> (-76.5, -63.5)
  curve K11 (-65, 103) -> (-76.5, 91.5)
  line L11 (65, 103) -> (-65, 103)
  curve K12 (76.5, 91.5) -> (65, 103)
  line L12 (76.5, -63.5) -> (76.5, 91.5)
  dimension "d951_1" = 0.5
extrude "Estrusione4" new body sketch "Schizzo5" profile of K5 L5 L8 L6 L7 K6 K7 K8 along normal blind 3 named "d952_1"
sketch "Schizzo2" plane through (-153.8, 0, 0) normal (-1, 0, 0) x axis (0, -1, 0)
  line L1 (83.1107, 91.5) -> (83.1107, -63.5)
  curve K1 (65, 109.6107) -> (83.1107, 91.5)
  line L2 (-65, 109.6107) -> (65, 109.6107)
  curve K2 (-83.1107, 91.5) -> (-65, 109.6107)
  line L3 (-83.1107, -63.5) -> (-83.1107, 91.5)
  curve K3 (-65, -81.6107) -> (-83.1107, -63.5)
  line L4 (65, -81.6107) -> (-65, -81.6107)
  curve K4 (83.1107, -63.5) -> (65, -81.6107)
  curve K5
  line L5 (-65, 110.1107) -> (65, 110.1107)
  curve K6 (-83.6107, 91.5) -> (-65, 110.1107)
  line L6 (-83.6107, -63.5) -> (-83.6107, 91.5)
  curve K7 (-65, -82.1107) -> (-83.6107, -63.5)
  line L7 (65, -82.1107) -> (-65, -82.1107)
  curve K8 (83.6107, -63.5) -> (65, -82.1107)
  line L8 (83.6107, 91.5) -> (83.6107, -63.5)
  curve K9 (65, 112.6107) -> (86.1107, 91.5)
  line L9 (-65, 112.6107) -> (65, 112.6107)
  curve K10 (-86.1107, 91.5) -> (-65, 112.6107)
  line L10 (-86.1107, -63.5) -> (-86.1107, 91.5)
  curve K11 (-65, -84.6107) -> (-86.1107, -63.5)
  line L11 (65, -84.6107) -> (-65, -84.6107)
  curve K12 (86.1107, -63.5) -> (65, -84.6107)
  line L12 (86.1107, 91.5) -> (86.1107, -63.5)
  dimension "d954_1" = 0.5
  dimension "d955_1" = 3
extrude "Estrusione2" add sketch "Schizzo2" profile of K5 L8 K6 L5 L6 K8 K7 L7 K9 L12 K10 L9 L10 K12 K11 L11 to an object
sketch "Schizzo3" plane through (-148.4, 0, 0) normal (1, 0, 0) x axis (0, 1, 0)
  curve K1 (65, 110.4651) -> (83.9651, 91.5)
  line L1 (-65, 110.4651) -> (65, 110.4651)
  curve K2 (-83.9651, 91.5) -> (-65, 110.4651)
  line L2 (-83.9651, -63.5) -> (-83.9651, 91.5)
  curve K3 (-65, -82.4651) -> (-83.9651, -63.5)
  line L3 (65, -82.4651) -> (-65, -82.4651)
  curve K4 (83.9651, -63.5) -> (65, -82.4651)
  line L4 (83.9651, 91.5) -> (83.9651, -63.5)
  curve K5 (-76.5, -63.5) -> (-65, -75)
  line L5 (-76.5, 91.5) -> (-76.5, -63.5)
  curve K6 (-65, 103) -> (-76.5, 91.5)
  line L6 (65, 103) -> (-65, 103)
  curve K7 (76.5, 91.5) -> (65, 103)
  line L7 (76.5, -63.5) -> (76.5, 91.5)
  curve K8 (65, -75) -> (76.5, -63.5)
  line L8 (-65, -75) -> (65, -75)
  circle C1 centre (-81.5735, -43.5) radius 2
  circle C2 centre (-81.5735, 71.5) radius 2
  circle C3 centre (81.5735, 71.5) radius 2
  circle C4 centre (81.5735, -43.5) radius 2
  circle C5 centre (-81.5735, -43.5) radius 1.75
  circle C6 centre (-81.5735, 71.5) radius 1.75
  circle C7 centre (81.5735, 71.5) radius 1.75
  circle C8 centre (81.5735, -43.5) radius 1.75
  concentric C1 C5
  concentric C2 C6
  concentric C3 C7
  concentric C4 C8
  dimension "d958_1" diameter C5 = 3.5
  dimension "d959_1" diameter C6 = 3.5
  dimension "d960_1" diameter C7 = 3.5
  dimension "d961_1" diameter C8 = 3.5
extrude "Estrusione5" cut sketch "Schizzo3" profile of C5 C6 C7 C8 against normal blind 51.149 named "d962_1"
component_from_bodies "Corpo->Comp2"
fillet "Raccordo1" radius 0.5 named "d967_1"
sketch "Schizzo4" plane through (-148.4, 0, 0) normal (1, 0, 0) x axis (0, 1, 0)
  curve K1 (65, 110.4651) -> (83.9651, 91.5)
  line L1 (-65, 110.4651) -> (65, 110.4651)
  curve K2 (-83.9651, 91.5) -> (-65, 110.4651)
  line L2 (-83.9651, -63.5) -> (-83.9651, 91.5)
  curve K3 (-65, -82.4651) -> (-83.9651, -63.5)
  line L3 (65, -82.4651) -> (-65, -82.4651)
  curve K4 (83.9651, -63.5) -> (65, -82.4651)
  line L4 (83.9651, 91.5) -> (83.9651, -63.5)
  line L5 (-64.3, -78.7) -> (64.3, -78.7)
  curve K5 (-80.2, -62.8) -> (-64.3, -78.7)
  line L6 (-80.2, 90.8) -> (-80.2, -62.8)
  curve K6 (-64.3, 106.7) -> (-80.2, 90.8)
  line L7 (64.3, 106.7) -> (-64.3, 106.7)
  curve K7 (80.2, 90.8) -> (64.3, 106.7)
  line L8 (80.2, -62.8) -> (80.2, 90.8)
  curve K8 (64.3, -78.7) -> (80.2, -62.8)
  curve K9 (-76.5, -63.5) -> (-65, -75)
  line L9 (-76.5, 91.5) -> (-76.5, -63.5)
  curve K10 (-65, 103) -> (-76.5, 91.5)
  line L10 (65, 103) -> (-65, 103)
  curve K11 (76.5, 91.5) -> (65, 103)
  line L11 (76.5, -63.5) -> (76.5, 91.5)
  curve K12 (65, -75) -> (76.5, -63.5)
  line L12 (-65, -75) -> (65, -75)
  circle C1 centre (-81.5735, 71.5) radius 1.75
  circle C2 centre (81.5735, 71.5) radius 1.75
  circle C3 centre (-81.5735, -43.5) radius 1.75
  circle C4 centre (81.5735, -43.5) radius 1.75
  circle C5 centre (0, 108.0735) radius 1.1933
  circle C6 centre (45, 108.0735) radius 1.1933
  circle C7 centre (81.5735, 71.5) radius 1.1933
  circle C8 centre (81.5735, 14) radius 1.1933
  point P22 (80.2, 71.5)
  point P23 (44.1, 106.7)
  point P24 (0, 106.7)
  point P25 (80.2, 14)
  coincident L8 P22
  coincident L7 P23
  midpoint L7 P24
  midpoint L8 P25
  dimension "d980_1" distance L7 L10 = 3.7
  dimension "d981_1" distance L8 L11 = 3.7 (= "d980_1")
  dimension "d982_1" distance L6 L9 = 3.7 (= "d980_1")
  dimension "d983_1" distance L5 L12 = 3.7 (= "d981_1")
hole "Foratura1" HoleDepth 100 named "d969_1" HoleDiameter 3.5 named "d970_1" TipAngle 118 named "d971_1" CSDiameter 6.7 named "d972_1" CSAngle 90 named "d973_1"
mirror "Specchio1" mirrorStitchTolerance 0.1 named "d985_1"
work_plane "Piano di lavoro1"
mirror "Specchio2" mirrorStitchTolerance 0.1 named "d989_1"
sketch "Schizzo1" plane through (-153.8, 0, 0) normal (-1, 0, 0) x axis (0, -1, 0)
  line L1 (-83.1107, -63.5) -> (-83.1107, -45.4967)
  curve K1 (-65, -81.6107) -> (-83.1107, -63.5)
  line L2 (65, -81.6107) -> (-65, -81.6107)
  curve K2 (83.1107, -63.5) -> (65, -81.6107)
  line L3 (83.1107, -45.4967) -> (83.1107, -63.5)
  line L4 (83.1107, 69.5033) -> (83.1107, -41.5033)
  line L5 (83.1107, 91.5) -> (83.1107, 73.4967)
  curve K3 (65, 109.6107) -> (83.1107, 91.5)
  line L6 (-65, 109.6107) -> (65, 109.6107)
  curve K4 (-83.1107, 91.5) -> (-65, 109.6107)
  line L7 (-83.1107, 73.4967) -> (-83.1107, 91.5)
  line L8 (-83.1107, -41.5033) -> (-83.1107, 69.5033)
  line L9 (-83.1107, 14) -> (83.1107, 14)
  line L10 (0, 109.6107) -> (0, -81.6107)
  line L11 (42.5, -33.5) -> (-42.5, -33.5)
  line L12 (42.5, 61.5) -> (42.5, -33.5)
  line L13 (-42.5, 61.5) -> (42.5, 61.5)
  line L14 (-42.5, -33.5) -> (-42.5, 61.5)
  line L15 (42.5, 61.5) -> (-42.5, -33.5)
  line L16 (-42.5, 61.5) -> (42.5, -33.5)
  circle C1 centre (44.1, -78.7) radius 1.75
  circle C2 centre (44.1, 106.7) radius 1.75
  arc A1 centre (-82.6107, -41.5033) radius 0.5 clockwise from (-82.3802, -41.947) to (-83.1107, -41.5033)
  arc A2 centre (-81.5735, -43.5) radius 1.75 clockwise from (-82.3802, -41.947) to (-82.3802, -45.053)
  arc A3 centre (-82.6107, -45.4967) radius 0.5 clockwise from (-83.1107, -45.4967) to (-82.3802, -45.053)
  arc A4 centre (82.6107, -45.4967) radius 0.5 clockwise from (82.3802, -45.053) to (83.1107, -45.4967)
  arc A5 centre (81.5735, -43.5) radius 1.75 clockwise from (82.3802, -45.053) to (82.3802, -41.947)
  arc A6 centre (82.6107, -41.5033) radius 0.5 clockwise from (83.1107, -41.5033) to (82.3802, -41.947)
  arc A7 centre (82.6107, 69.5033) radius 0.5 clockwise from (82.3802, 69.947) to (83.1107, 69.5033)
  arc A8 centre (81.5735, 71.5) radius 1.75 clockwise from (82.3802, 69.947) to (82.3802, 73.053)
  arc A9 centre (82.6107, 73.4967) radius 0.5 clockwise from (83.1107, 73.4967) to (82.3802, 73.053)
  arc A10 centre (-82.6107, 73.4967) radius 0.5 clockwise from (-82.3802, 73.053) to (-83.1107, 73.4967)
  arc A11 centre (-81.5735, 71.5) radius 1.75 clockwise from (-82.3802, 73.053) to (-82.3802, 69.947)
  arc A12 centre (-82.6107, 69.5033) radius 0.5 clockwise from (-83.1107, 69.5033) to (-82.3802, 69.947)
  circle C3 centre (-44.1, 106.7) radius 1.75
  circle C4 centre (-44.1, -78.7) radius 1.75
  circle C5 centre (0, -78.7) radius 1.75
  circle C6 centre (80.2, 14) radius 1.75
  circle C7 centre (0, 106.7) radius 1.75
  circle C8 centre (-80.2, 14) radius 1.75
  point P40 (83.1107, 14)
  point P41 (-83.1107, 14)
  point P42 (0, -81.6107)
  point P43 (0, 109.6107)
  point P48 (0, 14)
  point P46 (42.5, 61.5)
  point P47 (-42.5, 61.5)
  point P44 (-42.5, -33.5)
  midpoint L4 P40
  midpoint L8 P41
  midpoint L2 P42
  midpoint L6 P43
  horizontal L11
  perpendicular L11 L12
  parallel L11 L13
  parallel L12 L14
  coincident L15 P48
  coincident L16 P48
  midpoint L9 P48
  dimension "d992_1" distance P46 P47 = 85
  dimension "d993_1" distance P44 P47 = 95
sketch "Schizzo2" plane through (-150.8, 0, 0) normal (1, 0, 0) x axis (0, 1, 0)
  line L1 (83.1107, 69.5033) -> (83.1107, -41.5033)
  line L2 (83.1107, 91.5) -> (83.1107, 73.4967)
  curve K1 (65, 109.6107) -> (83.1107, 91.5)
  line L3 (-65, 109.6107) -> (65, 109.6107)
  curve K2 (-83.1107, 91.5) -> (-65, 109.6107)
  line L4 (-83.1107, 73.4967) -> (-83.1107, 91.5)
  line L5 (-83.1107, -41.5033) -> (-83.1107, 69.5033)
  line L6 (-83.1107, -63.5) -> (-83.1107, -45.4967)
  curve K3 (-65, -81.6107) -> (-83.1107, -63.5)
  line L7 (65, -81.6107) -> (-65, -81.6107)
  curve K4 (83.1107, -63.5) -> (65, -81.6107)
  line L8 (83.1107, -45.4967) -> (83.1107, -63.5)
  line L9 (20, 10.5) -> (20, -9)
  line L10 (-20, 10.5) -> (20, 10.5)
  line L11 (-20, -28.5) -> (-20, -9)
  line L12 (20, -28.5) -> (-20, -28.5)
  line L13 (20, 22.5) -> (-20, 22.5)
  line L14 (-20, 47.5) -> (20, 47.5)
  line L15 (20, 35) -> (-20, 35)
  line L16 (-10, 22.5) -> (10, 22.5)
  line L17 (10, 47.5) -> (-10, 47.5)
  circle C1 centre (-44.1, -78.7) radius 1.75
  circle C2 centre (-44.1, 106.7) radius 1.75
  arc A1 centre (82.6107, -41.5033) radius 0.5 clockwise from (83.1107, -41.5033) to (82.3802, -41.947)
  arc A2 centre (82.6107, 69.5033) radius 0.5 clockwise from (82.3802, 69.947) to (83.1107, 69.5033)
  arc A3 centre (81.5735, 71.5) radius 1.75 clockwise from (82.3802, 69.947) to (82.3802, 73.053)
  arc A4 centre (82.6107, 73.4967) radius 0.5 clockwise from (83.1107, 73.4967) to (82.3802, 73.053)
  arc A5 centre (-82.6107, 73.4967) radius 0.5 clockwise from (-82.3802, 73.053) to (-83.1107, 73.4967)
  arc A6 centre (-81.5735, 71.5) radius 1.75 clockwise from (-82.3802, 73.053) to (-82.3802, 69.947)
  arc A7 centre (-82.6107, 69.5033) radius 0.5 clockwise from (-83.1107, 69.5033) to (-82.3802, 69.947)
  arc A8 centre (-82.6107, -41.5033) radius 0.5 clockwise from (-82.3802, -41.947) to (-83.1107, -41.5033)
  arc A9 centre (-81.5735, -43.5) radius 1.75 clockwise from (-82.3802, -41.947) to (-82.3802, -45.053)
  arc A10 centre (-82.6107, -45.4967) radius 0.5 clockwise from (-83.1107, -45.4967) to (-82.3802, -45.053)
  arc A11 centre (82.6107, -45.4967) radius 0.5 clockwise from (82.3802, -45.053) to (83.1107, -45.4967)
  arc A12 centre (81.5735, -43.5) radius 1.75 clockwise from (82.3802, -45.053) to (82.3802, -41.947)
  arc A13 centre (20, 35) radius 12.5 clockwise from (20, 47.5) to (20, 22.5)
  arc A14 centre (-20, 35) radius 12.5 clockwise from (-20, 22.5) to (-20, 47.5)
  circle C3 centre (44.1, 106.7) radius 1.75
  circle C4 centre (-36, 53) radius 1.875
  circle C5 centre (36, 53) radius 1.875
  circle C6 centre (36, -25) radius 1.725
  circle C7 centre (-36, -25) radius 1.725
  circle C8 centre (-20, -9) radius 19.5
  circle C9 centre (20, -9) radius 19.5
  arc A15 centre (-20, 35) radius 12.5 clockwise from (-30.2413, 27.833) to (-30.2413, 42.167)
  arc A16 centre (20, 35) radius 12.5 clockwise from (30.2413, 42.167) to (30.2413, 27.833)
  circle C10 centre (44.1, -78.7) radius 1.75
  circle C11 centre (0, -78.7) radius 1.75
  circle C12 centre (-80.2, 14) radius 1.75
  circle C13 centre (0, 106.7) radius 1.75
  circle C14 centre (80.2, 14) radius 1.75
  vertical L9
  perpendicular L10 L11
  tangent L13 A13
  tangent A13 L14
  parallel L13 L14
  tangent L14 A14
  tangent L13 A14
  horizontal L15
extrude "Estrusione1" cut sketch "Schizzo2" profile of L10 L12 L13 A13 L14 A14 C8 C9 A15 A16 L16 L17 against normal blind 36.794 named "d1002_1"
sketch "Schizzo6" plane through (-153.8, 0, 0) normal (-1, 0, 0) x axis (0, -1, 0)
  line L1 (20, 10.5) -> (-20, 10.5)
  line L2 (-20, -28.5) -> (20, -28.5)
  line L3 (-20, 22.5) -> (20, 22.5)
  line L4 (20, 47.5) -> (-20, 47.5)
  line L5 (-83.1107, -63.5) -> (-83.1107, -45.4967)
  curve K1 (-65, -81.6107) -> (-83.1107, -63.5)
  line L6 (65, -81.6107) -> (-65, -81.6107)
  curve K2 (83.1107, -63.5) -> (65, -81.6107)
  line L7 (83.1107, -45.4967) -> (83.1107, -63.5)
  line L8 (83.1107, 69.5033) -> (83.1107, -41.5033)
  line L9 (83.1107, 91.5) -> (83.1107, 73.4967)
  curve K3 (65, 109.6107) -> (83.1107, 91.5)
  line L10 (-65, 109.6107) -> (65, 109.6107)
  curve K4 (-83.1107, 91.5) -> (-65, 109.6107)
  line L11 (-83.1107, 73.4967) -> (-83.1107, 91.5)
  line L12 (-83.1107, -41.5033) -> (-83.1107, 69.5033)
  line L13 (83.6107, -63.5) -> (83.6107, 91.5)
  curve K5 (65, -82.1107) -> (83.6107, -63.5)
  line L14 (-65, -82.1107) -> (65, -82.1107)
  curve K6 (-83.6107, -63.5) -> (-65, -82.1107)
  line L15 (-83.6107, 91.5) -> (-83.6107, -63.5)
  curve K7
  line L16 (65, 110.1107) -> (-65, 110.1107)
  curve K8 (83.6107, 91.5) -> (65, 110.1107)
  line L17 (65, 111.7507) -> (-65, 111.7507)
  curve K9 (-65, 111.7507) -> (-85.2507, 91.5)
  line L18 (-85.2507, 91.5) -> (-85.2507, -63.5)
  curve K10 (-85.2507, -63.5) -> (-65, -83.7507)
  line L19 (-65, -83.7507) -> (65, -83.7507)
  curve K11 (65, -83.7507) -> (85.2507, -63.5)
  line L20 (85.2507, -63.5) -> (85.2507, 91.5)
  curve K12 (85.2507, 91.5) -> (65, 111.7507)
  line L21 (84.9507, -63.5) -> (84.9507, 91.5)
  curve K13 (65, -83.4507) -> (84.9507, -63.5)
  line L22 (-65, -83.4507) -> (65, -83.4507)
  curve K14 (-84.9507, -63.5) -> (-65, -83.4507)
  line L23 (-84.9507, 91.5) -> (-84.9507, -63.5)
  curve K15 (-65, 111.4507) -> (-84.9507, 91.5)
  line L24 (65, 111.4507) -> (-65, 111.4507)
  curve K16 (84.9507, 91.5) -> (65, 111.4507)
  line L25 (77.2507, -63.5) -> (77.2507, 91.5)
  curve K17 (65, -75.7507) -> (77.2507, -63.5)
  line L26 (-65, -75.7507) -> (65, -75.7507)
  curve K18 (-77.2507, -63.5) -> (-65, -75.7507)
  line L27 (-77.2507, 91.5) -> (-77.2507, -63.5)
  curve K19 (-65, 103.7507) -> (-77.2507, 91.5)
  line L28 (65, 103.7507) -> (-65, 103.7507)
  curve K20 (77.2507, 91.5) -> (65, 103.7507)
  arc A1 centre (-20, 35) radius 12.5 clockwise from (-20, 22.5) to (-20, 47.5)
  arc A2 centre (20, 35) radius 12.5 clockwise from (20, 47.5) to (20, 22.5)
  circle C1 centre (44.1, -78.7) radius 1.75
  circle C2 centre (44.1, 106.7) radius 1.75
  arc A3 centre (-82.6107, -41.5033) radius 0.5 clockwise from (-82.3802, -41.947) to (-83.1107, -41.5033)
  arc A4 centre (-81.5735, -43.5) radius 1.75 clockwise from (-82.3802, -41.947) to (-82.3802, -45.053)
  arc A5 centre (-82.6107, -45.4967) radius 0.5 clockwise from (-83.1107, -45.4967) to (-82.3802, -45.053)
  arc A6 centre (82.6107, -45.4967) radius 0.5 clockwise from (82.3802, -45.053) to (83.1107, -45.4967)
  arc A7 centre (81.5735, -43.5) radius 1.75 clockwise from (82.3802, -45.053) to (82.3802, -41.947)
  arc A8 centre (82.6107, -41.5033) radius 0.5 clockwise from (83.1107, -41.5033) to (82.3802, -41.947)
  arc A9 centre (82.6107, 69.5033) radius 0.5 clockwise from (82.3802, 69.947) to (83.1107, 69.5033)
  arc A10 centre (81.5735, 71.5) radius 1.75 clockwise from (82.3802, 69.947) to (82.3802, 73.053)
  arc A11 centre (82.6107, 73.4967) radius 0.5 clockwise from (83.1107, 73.4967) to (82.3802, 73.053)
  arc A12 centre (-82.6107, 73.4967) radius 0.5 clockwise from (-82.3802, 73.053) to (-83.1107, 73.4967)
  arc A13 centre (-81.5735, 71.5) radius 1.75 clockwise from (-82.3802, 73.053) to (-82.3802, 69.947)
  arc A14 centre (-82.6107, 69.5033) radius 0.5 clockwise from (-83.1107, 69.5033) to (-82.3802, 69.947)
  arc A15 centre (-20, -9) radius 19.5 clockwise from (-20, -28.5) to (-20, 10.5)
  arc A16 centre (20, -9) radius 19.5 clockwise from (20, 10.5) to (20, -28.5)
  circle C3 centre (-44.1, 106.7) radius 1.75
  circle C4 centre (-44.1, -78.7) radius 1.75
  circle C5 centre (0, -78.7) radius 1.75
  circle C6 centre (80.2, 14) radius 1.75
  circle C7 centre (0, 106.7) radius 1.75
  circle C8 centre (-80.2, 14) radius 1.75
  dimension "d1004_1" = 0.3
  dimension "d1005_1" = 8
extrude "Estrusione6" new body sketch "Schizzo6" profile of C1 C2 A3 A4 A5 L5 K1 L6 K2 L7 A6 A7 A8 L8 A9 A10 A11 L9 K3 L10 K4 L11 A12 A13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 along normal blind 3 named "d1006_1"
component_from_bodies "Corpo->Comp3"
thread "Filettatura1"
